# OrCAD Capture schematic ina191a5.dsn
size A
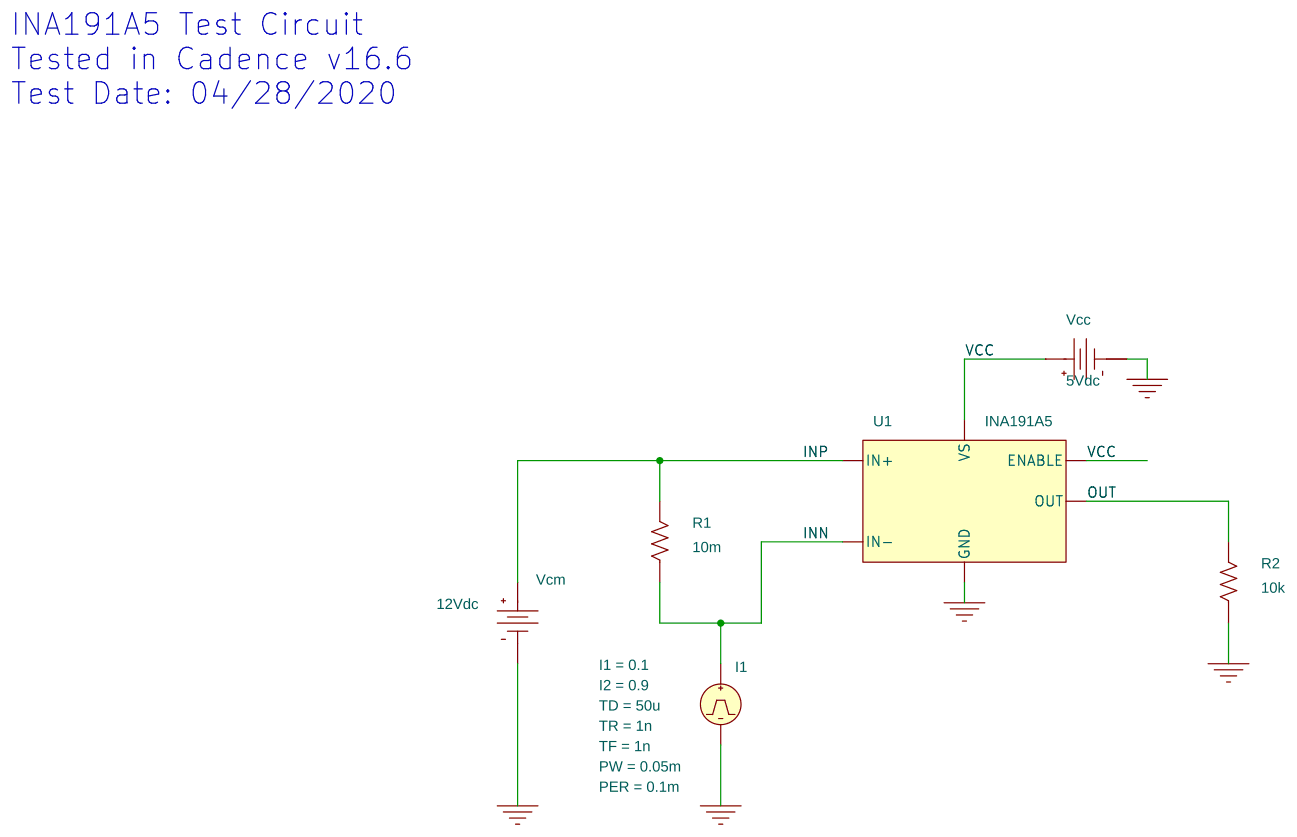
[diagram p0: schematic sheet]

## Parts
I1  IPULSE
R1  10m  [AX/RC05]
R2  10k  [AX/RC05]
U1  INA191A5
Vcc  VDC
Vcm  VDC

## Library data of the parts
I1 = IPULSE: I1: 0.1; I2: 0.9; PER: 0.1m; PW: 0.05m; TD: 50u; TF: 1n; TR: 1n
R1 R2 = R
U1 = INA191A5
Vcc = VDC: DC: 5Vdc
Vcm = VDC: DC: 12Vdc

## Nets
VCC: U1.ENABLE U1.VS Vcc.0(+)
0: I1.2(-) R2.1 U1.GND Vcc.1(-) Vcm.1(-)
INN: I1.1(+) R1.1 U1.IN-
INP: R1.2 U1.IN+ Vcm.0(+)
OUT: R2.2 U1.OUT

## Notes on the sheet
- INA191A5 Test Circuit
  Tested in Cadence v16.6
  Test Date: 04/28/2020
